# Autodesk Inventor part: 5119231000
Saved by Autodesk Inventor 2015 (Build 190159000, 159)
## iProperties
Created: 2020-07
Part Number: 5119231000
Checked By: TraceParts S.A.
Material: Generic
Catalog Web Link: www.traceparts.com
Document SubType Name: Modeling
Designer: TraceParts
Density: 1 g/cm^3
Appearance: Default
Company: TraceParts S.A.
Author: TraceParts
REFERENCE: 5119231000
DESIGN: HIT-1250 P 1,1KW (230/400V 50HZ) - 5119231000
SUPPLIER: Soler & Palau
TraceParts.PartNumber: 10-20122018-119595
TraceParts.PartTitle: HIB-P/HIT-P
TraceParts.InstanceId: 10-20122018-119595100UZG559OTB61TV84Y0DIKUU
TraceParts.PartStatus: Published
TraceParts.PartVersion: 1.0.2
TRACEPARTS: TRACEPARTS
TraceParts.PartLanguage: en
TraceParts.ClassPath: SOLER_PALAU:10-20122018-119595
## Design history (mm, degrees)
feature "5119231000"
body "Solid1"
